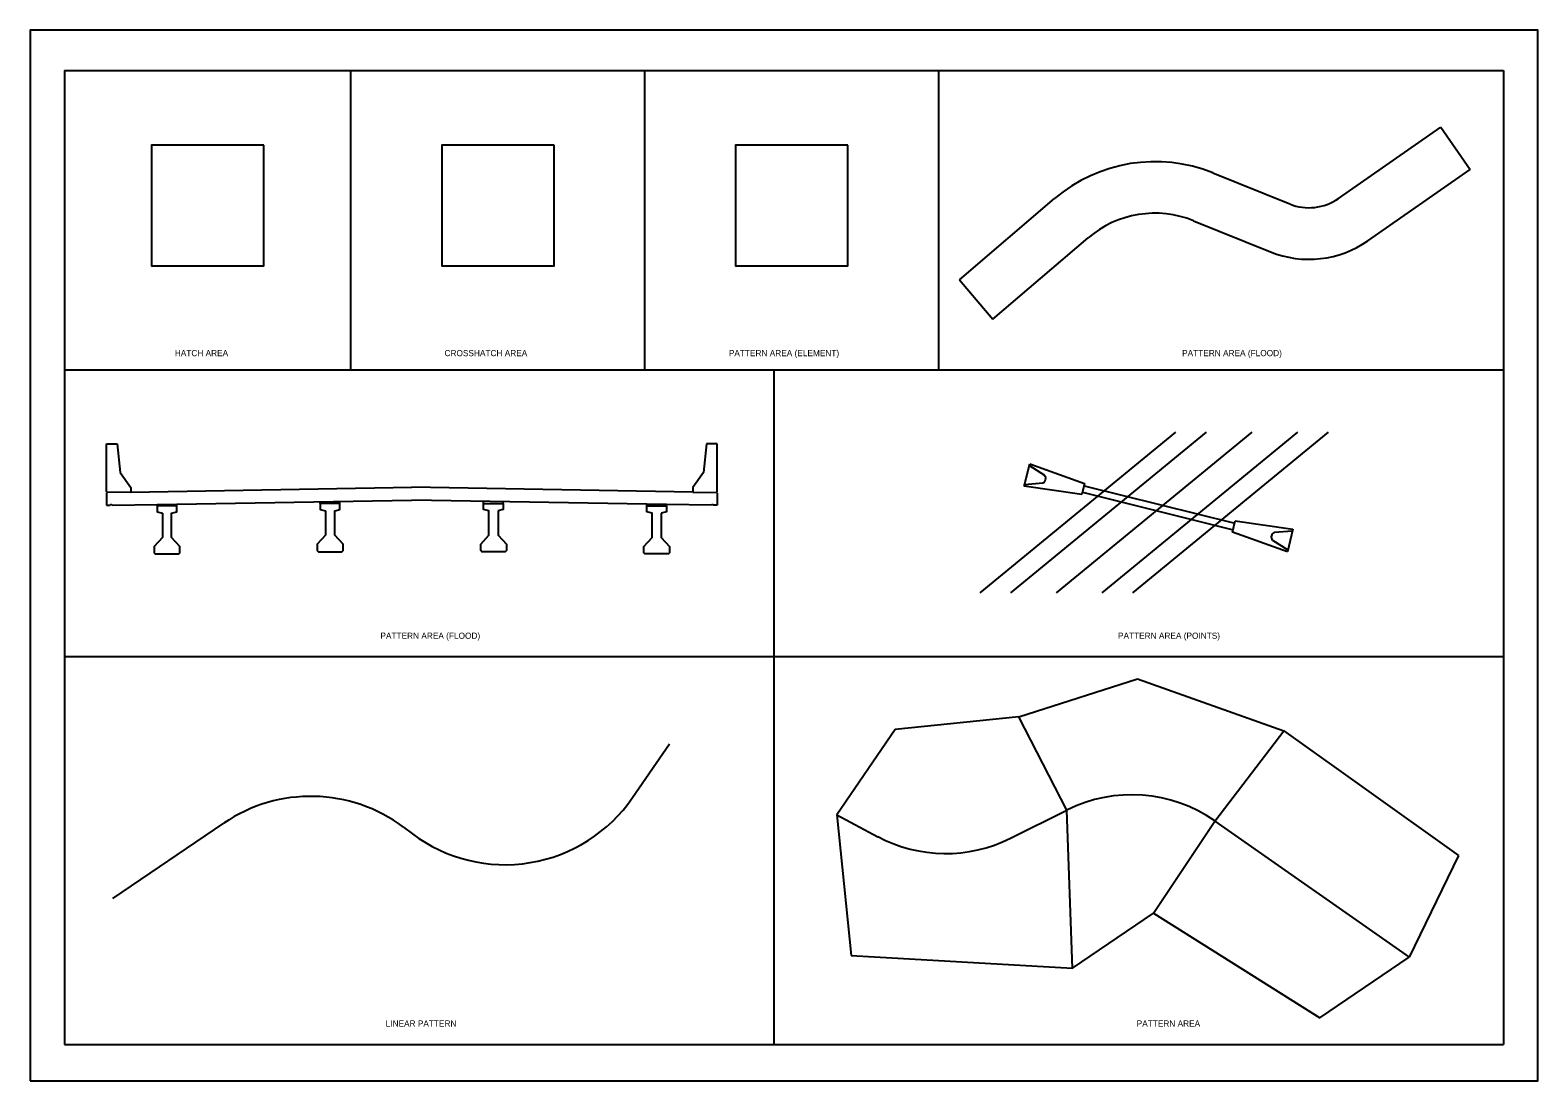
# Model space of a CAD drawing. Extents: x -1415 to 1510, y -2580 to -543.
import ezdxf

# ---------------------------------------------------------------- set-up
doc = ezdxf.new("R2010")
doc.units = 0
for name, color, linetype in [('Bridge-Concrete', 7, 'Continuous'), ('Draft_Named_Boundary', 7, 'Continuous'), ('Drainage-Structures', 7, 'Continuous'), ('Level 1', 7, 'Continuous'), ('Level 2', 7, 'Continuous'), ('Roadway-Centerline main', 7, 'Continuous'), ('Roadway-Edge of pavement', 7, 'Continuous'), ('Roadway-Edge of shoulder', 7, 'Continuous')]:
    doc.layers.add(name, color=color, linetype=linetype)

msp = doc.modelspace()

# ---------------------------------------------------------------- linework, layer by layer
at = {"layer": 'Bridge-Concrete'}
for p, q in [((-1266.3, -1344.9), (-1245.8, -1344.9)), ((-1266.3, -1438.3), (-1266.3, -1344.9)), ((-1245.8, -1344.9), (-1240, -1400.6)), ((-102.8, -1344.9), (-108.7, -1400.6)), ((-82.3, -1344.9), (-102.8, -1344.9)), ((-82.3, -1438.3), (-82.3, -1344.9)), ((-1240, -1400.6), (-1219.5, -1429.9)), ((-108.7, -1400.6), (-129.2, -1429.9)), ((-1219.5, -1438.7), (-674.3, -1429.1)), ((-1219.5, -1429.9), (-1219.5, -1438.7)), ((-129.2, -1438.7), (-674.3, -1429.1)), ((-129.2, -1429.9), (-129.2, -1438.7)), ((-1265.2, -1439.4), (-1266.3, -1438.3)), ((-1265.2, -1439.4), (-1266.3, -1440.5)), ((-1266.3, -1440.5), (-1266.3, -1464.3)), ((-1219.5, -1438.7), (-1265.2, -1439.4)), ((-1257.5, -1462), (-1259.7, -1464.2)), ((-1257.5, -1462), (-1255.3, -1464.1)), ((-1168.2, -1462.8), (-674.3, -1454)), ((-1130.1, -1465), (-1130.1, -1462)), ((-851.8, -1460.5), (-851.8, -1457.2)), ((-813.7, -1460.5), (-813.7, -1456.5)), ((-180.5, -1462.8), (-674.3, -1454)), ((-535, -1460.5), (-535, -1456.5)), ((-496.9, -1460.5), (-496.9, -1457.2)), ((-218.6, -1465), (-218.6, -1462)), ((-129.2, -1438.7), (-83.4, -1439.4)), ((-91.1, -1462), (-93.3, -1464.1)), ((-91.1, -1462), (-88.9, -1464.2)), ((-83.4, -1439.4), (-82.3, -1438.3)), ((-83.4, -1439.4), (-82.3, -1440.5)), ((-82.3, -1440.5), (-82.3, -1464.3)), ((-1266.3, -1464.3), (-1259.7, -1464.2)), ((-1255.3, -1464.1), (-1168.2, -1462.8)), ((-1168.2, -1465), (-1168.2, -1462.8)), ((-180.5, -1465), (-180.5, -1462.8)), ((-93.3, -1464.1), (-180.5, -1462.8)), ((-82.3, -1464.3), (-88.9, -1464.2))]:
    msp.add_line(p, q, dxfattribs=at)
for points in [[(-841.5, -1475.1), (-841.5, -1522), (-857.6, -1539.6), (-857.6, -1552), (-855.4, -1554.2), (-810, -1554.2), (-807.8, -1552), (-807.8, -1539.6), (-823.9, -1522), (-823.9, -1475.1), (-813.7, -1472.2), (-813.7, -1460.5), (-851.8, -1460.5), (-851.8, -1472.2), (-841.5, -1475.1)], [(-507.1, -1475.1), (-507.1, -1522), (-491, -1539.6), (-491, -1552), (-493.2, -1554.2), (-538.6, -1554.2), (-540.8, -1552), (-540.8, -1539.6), (-524.7, -1522), (-524.7, -1475.1), (-535, -1472.2), (-535, -1460.5), (-496.9, -1460.5), (-496.9, -1472.2), (-507.1, -1475.1)], [(-1157.9, -1479.6), (-1157.9, -1526.5), (-1174, -1544.1), (-1174, -1556.5), (-1171.8, -1558.7), (-1126.4, -1558.7), (-1124.2, -1556.5), (-1124.2, -1544.1), (-1140.4, -1526.5), (-1140.4, -1479.6), (-1130.1, -1476.7), (-1130.1, -1465), (-1168.2, -1465), (-1168.2, -1476.7), (-1157.9, -1479.6)], [(-190.7, -1479.6), (-190.7, -1526.5), (-174.6, -1544.1), (-174.6, -1556.5), (-176.8, -1558.7), (-222.2, -1558.7), (-224.4, -1556.5), (-224.4, -1544.1), (-208.3, -1526.5), (-208.3, -1479.6), (-218.6, -1476.7), (-218.6, -1465), (-180.5, -1465), (-180.5, -1476.7), (-190.7, -1479.6)]]:
    msp.add_lwpolyline(points, dxfattribs=at)
at = {"layer": 'Draft_Named_Boundary'}
msp.add_lwpolyline([(-1414.6, -2580.4), (1509.6, -2580.4), (1509.6, -542.9), (-1414.6, -542.9)], close=True, dxfattribs=at)
at = {"layer": 'Drainage-Structures'}
for p, q in [((513.2, -1427.3), (524, -1383.6)), ((553.2, -1406.4), (523.1, -1387.3)), ((524, -1383.6), (630.5, -1421.7)), ((625.1, -1443.6), (513.2, -1427.3)), ((514.1, -1423.7), (549.5, -1420.9)), ((630.5, -1421.7), (625.1, -1443.6)), ((629.4, -1426.3), (921.7, -1499)), ((626.2, -1439), (918.5, -1511.8)), ((917.4, -1516.3), (922.8, -1494.5)), ((1023.8, -1554.4), (917.4, -1516.3)), ((922.8, -1494.5), (1034.7, -1510.8)), ((1033.8, -1514.4), (998.3, -1517.2)), ((1034.7, -1510.8), (1023.8, -1554.4)), ((994.7, -1531.7), (1024.7, -1550.8))]:
    msp.add_line(p, q, dxfattribs=at)
for centre, start, end in [((545.9, -1412.3), 292.8925, 39.1527), ((1002, -1525.8), 112.8925, 219.1527)]:
    msp.add_arc(centre, 9.37, start, end, dxfattribs=at)
at = {"layer": 'Level 1'}
for p, q in [((503.1, -1874.3), (733.1, -1800.7)), ((733.1, -1800.7), (1017, -1901.4)), ((263.2, -1898.8), (149.9, -2064.8)), ((503.1, -1874.3), (263.2, -1898.8)), ((596.3, -2055.2), (503.1, -1874.3)), ((883.3, -2076.5), (1017, -1901.4)), ((1017, -1901.4), (1355.8, -2143.3)), ((149.9, -2064.8), (177.9, -2337.4)), ((606.9, -2361.8), (596.3, -2055.2)), ((764.4, -2255.2), (883.3, -2076.5)), ((1355.8, -2143.3), (1260.2, -2340.4)), ((606.9, -2361.8), (764.4, -2255.2)), ((764.4, -2255.2), (1086.8, -2457.9)), ((177.9, -2337.4), (606.9, -2361.8)), ((1086.8, -2457.9), (1260.2, -2340.4))]:
    msp.add_line(p, q, dxfattribs=at)
at = {"layer": 'Level 2'}
for p, q in [((-1348.1, -620.8), (1443.2, -620.8)), ((-1348.1, -620.8), (-1348.1, -2509.6)), ((-792.4, -1201.4), (-792.4, -620.8)), ((-222.4, -1201.4), (-222.4, -620.8)), ((347.6, -1201.4), (347.6, -620.8)), ((1443.2, -620.8), (1443.2, -2509.6)), ((1122.9, -869.3), (1321.3, -731.1)), ((1321.3, -731.1), (1378.4, -813.1)), ((1180.1, -951.3), (1378.4, -813.1)), ((879.5, -819.8), (1028.3, -879.9)), ((387.7, -1027), (572.4, -869.6)), ((842, -912.5), (990.8, -972.6)), ((452.6, -1103.1), (637.3, -945.7)), ((387.7, -1027), (452.6, -1103.1)), ((-1348.1, -1201.4), (1443.2, -1201.4)), ((27.6, -1201.4), (27.6, -1757.5)), ((-1348.1, -1757.5), (1443.2, -1757.5)), ((27.6, -1757.5), (27.6, -2509.6)), ((-246.2, -2031.2), (-174.4, -1926.8)), ((-1254.1, -2227), (-1038.9, -2080.6)), ((-690.3, -2088.5), (-673.3, -2101.3)), ((-1348.1, -2509.6), (1443.2, -2509.6))]:
    msp.add_line(p, q, dxfattribs=at)
for points in [[(-961.3, -765.6), (-1179.2, -765.6), (-1179.2, -999.7), (-961.3, -999.7)], [(-398.5, -765.6), (-616.4, -765.6), (-616.4, -999.7), (-398.5, -999.7)], [(171.5, -765.6), (-46.4, -765.6), (-46.4, -999.7), (171.5, -999.7)]]:
    msp.add_lwpolyline(points, close=True, dxfattribs=at)
for centre, radius, start, end in [((767, -1097.9), 300, 67.9776, 130.4419), ((1065.8, -787.2), 100, 247.9776, 304.8695), ((767, -1097.9), 200, 67.9776, 130.4419), ((1065.8, -787.2), 200, 247.9776, 304.8695), ((-870.2, -2328.7), 300, 53.1684, 124.2204), ((-493.4, -1861.2), 300, 233.1684, 325.4892)]:
    msp.add_arc(centre, radius, start, end, dxfattribs=at)
at = {"layer": 'Roadway-Centerline main'}
for p, q in [((576.1, -1633.8), (955.5, -1322.6)), ((149.9, -2064.8), (229.5, -2106.9)), ((486.7, -2110), (596.3, -2055.2)), ((883.3, -2076.5), (1260.2, -2340.4))]:
    msp.add_line(p, q, dxfattribs=at)
for centre, start, end in [((722, -2306.8), 54.9927, 116.5356), ((361, -1858.3), 242.1159, 296.5356)]:
    msp.add_arc(centre, 281.2, start, end, dxfattribs=at)
at = {"layer": 'Roadway-Edge of pavement'}
for p, q in [((487.4, -1633.8), (866.8, -1322.6)), ((664.7, -1633.8), (1044.2, -1322.6))]:
    msp.add_line(p, q, dxfattribs=at)
at = {"layer": 'Roadway-Edge of shoulder'}
for p, q in [((428.3, -1633.8), (807.7, -1322.6)), ((723.9, -1633.8), (1103.3, -1322.6))]:
    msp.add_line(p, q, dxfattribs=at)

# ---------------------------------------------------------------- texts
at = {"layer": 'Level 2'}
for s, p in [('HATCH AREA', (-1134, -1175.1)), ('CROSSHATCH AREA', (-610.9, -1175.1)), ('PATTERN AREA (ELEMENT)', (-59.5, -1175.1)), ('PATTERN AREA (FLOOD)', (819.7, -1175.1)), ('PATTERN AREA (FLOOD)', (-735.2, -1723.2)), ('PATTERN AREA (POINTS)', (695.3, -1723.2)), ('LINEAR PATTERN', (-725.1, -2475.2)), ('PATTERN AREA', (731.6, -2475.2))]:
    msp.add_text(s, height=12, dxfattribs=at).set_placement(p)

doc.saveas('drawing.dxf')
